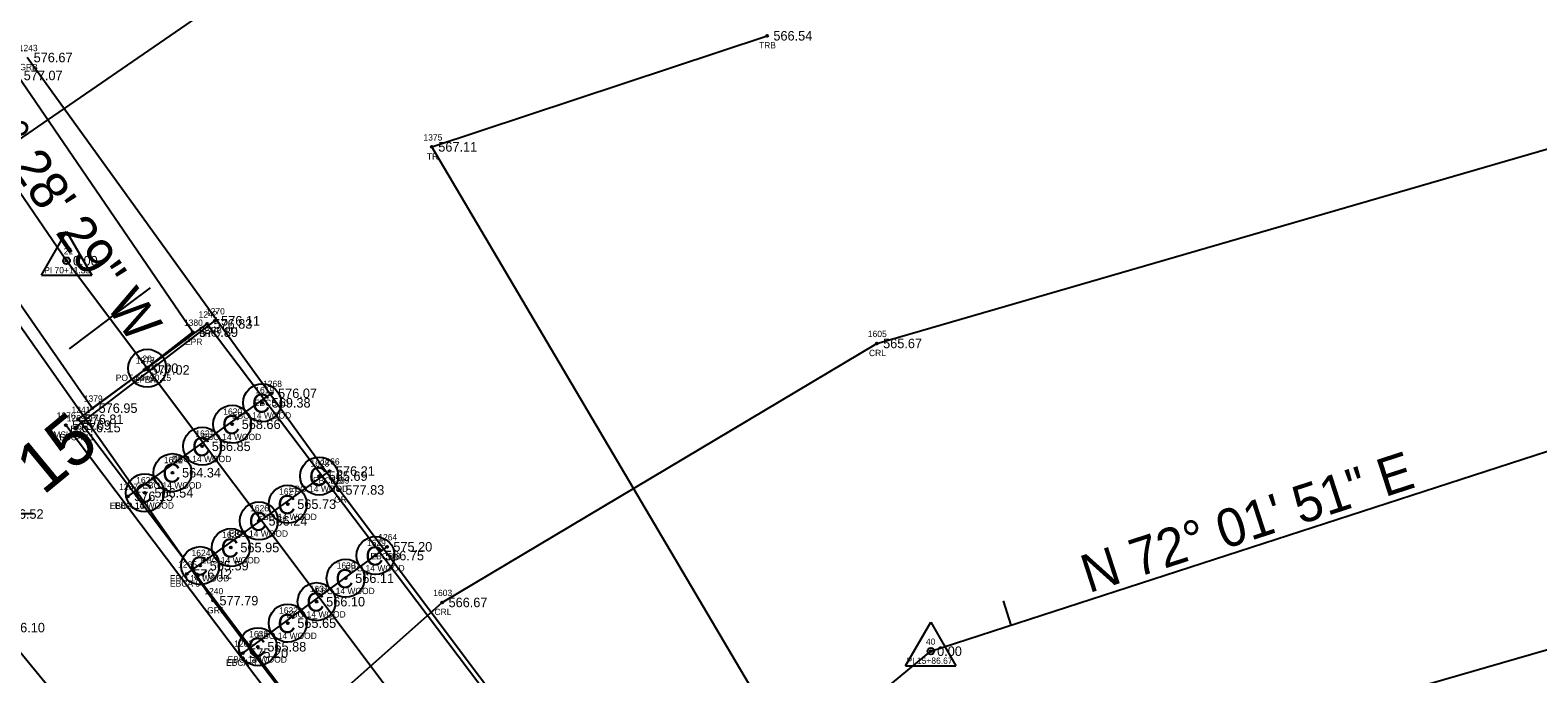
# Model space of a CAD drawing. Extents: x 1694813 to 1696862, y 1086485 to 1091027.
# Drawn here: x 1695795.8 to 1696033.6, y 1089100.2 to 1089201.7 of the extents above; entities that cross this region are included whole.
import ezdxf

# ---------------------------------------------------------------- set-up
doc = ezdxf.new("R2010")
doc.units = 0
for name, color, linetype in [('RD_EX_Bridge', 7, 'Continuous'), ('RD_EX_Bridge_txCode', 7, 'Continuous'), ('RD_EX_GuardRail', 7, 'Continuous'), ('RD_EX_GuardRail_txCode', 7, 'Continuous'), ('RD_EX_H2O', 7, 'Continuous'), ('RD_EX_H2O_txCode', 7, 'Continuous'), ('RD_EX_Misc', 7, 'Continuous'), ('RD_EX_Misc_txCode', 7, 'Continuous'), ('RD_EX_Road', 7, 'Continuous'), ('RD_EX_Road_txCode', 7, 'Continuous'), ('RD_EX_TX_Bridge_ELEV', 7, 'Continuous'), ('RD_EX_TX_GuardRail_ELEV', 7, 'Continuous'), ('RD_EX_TX_H2O_ELEV', 7, 'Continuous'), ('RD_EX_TX_Misc_ELEV', 7, 'Continuous'), ('RD_EX_TX_Road_ELEV', 7, 'Continuous'), ('RD_EX_TX_UT_ELEV', 7, 'Continuous'), ('RD_EX_TX_VEG_ELEV', 7, 'Continuous'), ('RD_EX_UT', 7, 'Continuous'), ('RD_EX_VEG', 7, 'Continuous'), ('RD_EX_VEG_txCode', 7, 'Continuous'), ('RD_HC_Cl', 7, 'Continuous'), ('RD_HC_Data', 7, 'Continuous'), ('RD_HC_Data_Tic', 7, 'Continuous'), ('RD_HC_Survey_ELEV', 7, 'Continuous'), ('RD_HC_TX_Sta50', 7, 'Continuous'), ('RD_HC_txCode', 7, 'Continuous'), ('RD_SMD_Locator', 7, 'Continuous')]:
    doc.layers.add(name, color=color, linetype=linetype)

msp = doc.modelspace()

# ---------------------------------------------------------------- linework, layer by layer
at = {"layer": 'RD_EX_Bridge'}
for p, q in [((1695802.9, 1089139.01), (1695824.88, 1089155.85)), ((1695811.17, 1089128.17), (1695833.87, 1089144.42)), ((1695820.47, 1089115.93), (1695842.99, 1089132.16)), ((1695829.32, 1089103.44), (1695852.05, 1089120.22))]:
    msp.add_line(p, q, dxfattribs=at)
msp.add_lwpolyline([(1695941.01, 1089000.23), (1695920.78, 1088984.87), (1695803.35, 1089140.32), (1695823.67, 1089155.36), (1695941.01, 1089000.23)], dxfattribs=at)
for centre in [(1695832.36, 1089142.92), (1695827.63, 1089139.53), (1695822.91, 1089136.06), (1695818.22, 1089131.9), (1695841.35, 1089131.36), (1695813.86, 1089128.72), (1695836.39, 1089126.93), (1695831.85, 1089124.29), (1695827.42, 1089120.09), (1695850.25, 1089118.83), (1695822.59, 1089117.24), (1695845.53, 1089115.25), (1695840.95, 1089111.56), (1695836.4, 1089108.18), (1695831.68, 1089104.45)]:
    msp.add_circle(centre, 3, dxfattribs=at)
at = {"layer": 'RD_EX_GuardRail'}
for points in [[(1695954.25, 1088939.4), (1695922.07, 1088982.8), (1695888.95, 1089026.55), (1695824.62, 1089111.72), (1695774.33, 1089183.16), (1695747.02, 1089230.32), (1695728.79, 1089274.77), (1695712.04, 1089332.59)], [(1695975.12, 1088955.36), (1695942.2, 1088999.47), (1695910.75, 1089040.94), (1695844.49, 1089129.18), (1695795.31, 1089197.37)]]:
    msp.add_lwpolyline(points, dxfattribs=at)
at = {"layer": 'RD_EX_H2O'}
for points in [[(1695741.44, 1088979.77), (1695766.31, 1089008.66), (1695772.21, 1089014.13), (1695837.09, 1089090.39), (1695860.76, 1089111.44), (1695929.31, 1089152.28), (1696035.3, 1089183.03), (1696164.17, 1089149.21), (1696221.7, 1089111.38), (1696248.95, 1089080.06), (1696273.19, 1089047.83), (1696283.59, 1089011.28), (1696295.68, 1088944.39)], [(1695520.92, 1088704.05), (1695627.53, 1088770.84), (1695697.51, 1088817.15), (1695757.08, 1088884.85), (1695828.4, 1088961.5), (1695887.69, 1089025.09), (1695910.13, 1089043.49), (1695963.83, 1089083.42), (1696041.69, 1089105.91), (1696137.07, 1089082.48), (1696174.24, 1089034.61), (1696185.76, 1089011.54), (1696200.45, 1088973.14), (1696214.06, 1088899.28)]]:
    msp.add_lwpolyline(points, dxfattribs=at)
at = {"layer": 'RD_EX_Misc'}
msp.add_line((1695918.59, 1088984.27), (1695801.38, 1089139.4), dxfattribs=at)
at = {"layer": 'RD_EX_Road'}
for points in [[(1695813.78, 1089148.1), (1695805.56, 1089142.08), (1695776.44, 1089183.94), (1695749.27, 1089231.88), (1695730.49, 1089275.72), (1695714.87, 1089332.12), (1695707.87, 1089381.72), (1695706.58, 1089435.34), (1695711.58, 1089484.26), (1695722.15, 1089537.59), (1695749.04, 1089634.88), (1695776.11, 1089730.43), (1695788.13, 1089777.42), (1695798.89, 1089826.76), (1695807.1, 1089870.03), (1695814.71, 1089923.3), (1695820.51, 1089978.16), (1695824.04, 1090019.79), (1695832.76, 1090119.06), (1695841.25, 1090216.76), (1695850.36, 1090314.41), (1695859.24, 1090411.82), (1695868.09, 1090511.63), (1695876.75, 1090608.38)], [(1695813.78, 1089148.1), (1695821.41, 1089154.05), (1695793.74, 1089194.54), (1695767.99, 1089240.85), (1695750.16, 1089282.55), (1695735.35, 1089335.84), (1695728.69, 1089383.6)]]:
    msp.add_lwpolyline(points, dxfattribs=at)
at = {"layer": 'RD_EX_UT'}
msp.add_line((1695792.25, 1089125.44), (1695796.27, 1089125.44), dxfattribs=at)
at = {"layer": 'RD_EX_VEG'}
for points in [[(1695767.04, 1087738.17), (1695850.84, 1087719.29), (1695876.92, 1087874.52), (1695886.77, 1087978.73), (1695882.04, 1088123.19), (1695966.35, 1088397.22), (1695987.61, 1088500.99), (1696016.82, 1088604.01), (1696023.94, 1088658.84), (1696026.75, 1088706.17), (1696020.44, 1088756.26), (1696012.04, 1088803.02), (1695995.69, 1088847.32), (1695967.16, 1088892.48), (1695790.95, 1089107.47), (1695767.01, 1089177.35), (1695741.24, 1089223.37), (1695720.39, 1089271.33), (1695703.52, 1089329.03), (1695695, 1089381.13)], [(1695933.86, 1087837.25), (1695947.67, 1087971.41), (1695951.18, 1088015.29), (1695955.07, 1088071.66), (1695974.95, 1088229.99), (1695984.06, 1088281.51), (1695991.57, 1088334), (1696002.15, 1088386.49), (1696032.05, 1088491.59), (1696059.12, 1088595.39), (1696074.06, 1088653.09), (1696077.62, 1088703.57), (1696070.4, 1088760.42), (1696059.88, 1088817.29), (1696044.37, 1088867.3), (1696013.5, 1088916.36), (1695990.24, 1088961.27), (1695859.14, 1089183.28), (1695912, 1089200.8)]]:
    msp.add_lwpolyline(points, dxfattribs=at)
at = {"layer": 'RD_HC_Cl'}
for p, q in [((1695801.51, 1089165.33), (1695790.19, 1089181.82)), ((1695971.3, 1088939.1), (1695801.51, 1089165.33)), ((1695937.83, 1089103.75), (1696039.29, 1089136.66)), ((1695799.79, 1088989.83), (1695937.83, 1089103.75))]:
    msp.add_line(p, q, dxfattribs=at)
at = {"layer": 'RD_HC_Data'}
for p, q in [((1695790.19, 1089181.82), (1695886.34, 1089247.84)), ((1695797.54, 1089163.04), (1695801.51, 1089169.92)), ((1695801.51, 1089169.92), (1695805.48, 1089163.04)), ((1695797.54, 1089163.04), (1695805.48, 1089163.04)), ((1695933.86, 1089101.46), (1695937.83, 1089108.34)), ((1695937.83, 1089108.34), (1695941.8, 1089101.46)), ((1695933.86, 1089101.46), (1695941.8, 1089101.46))]:
    msp.add_line(p, q, dxfattribs=at)
for centre, radius in [((1695801.51, 1089165.33), 0.529), ((1695814.23, 1089148.37), 3), ((1695814.23, 1089148.37), 0.282), ((1695937.83, 1089103.75), 0.529)]:
    msp.add_circle(centre, radius, dxfattribs=at)
at = {"layer": 'RD_HC_Data_Tic'}
for p, q in [((1695808.32, 1089156.25), (1695814.72, 1089161.05)), ((1695808.32, 1089156.25), (1695801.92, 1089151.45)), ((1695950.51, 1089107.86), (1695949.28, 1089111.67))]:
    msp.add_line(p, q, dxfattribs=at)
at = {"layer": 'RD_SMD_Locator'}
for centre in [(1695912, 1089200.8), (1695859.14, 1089183.28), (1695801.51, 1089165.33), (1695821.41, 1089154.05), (1695823.67, 1089155.36), (1695824.88, 1089155.85), (1695929.31, 1089152.28), (1695813.78, 1089148.1), (1695813.78, 1089148.1), (1695814.23, 1089148.37), (1695833.87, 1089144.42), (1695805.56, 1089142.08), (1695832.36, 1089142.92), (1695801.38, 1089139.4), (1695803.35, 1089140.32), (1695827.63, 1089139.53), (1695802.9, 1089139.01), (1695822.91, 1089136.06), (1695818.22, 1089131.9), (1695841.35, 1089131.36), (1695842.99, 1089132.16), (1695811.17, 1089128.17), (1695813.86, 1089128.72), (1695844.49, 1089129.18), (1695836.39, 1089126.93), (1695831.85, 1089124.29), (1695827.42, 1089120.09), (1695850.25, 1089118.83), (1695852.05, 1089120.22), (1695820.47, 1089115.93), (1695822.59, 1089117.24), (1695845.53, 1089115.25), (1695824.62, 1089111.72), (1695840.95, 1089111.56), (1695860.76, 1089111.44), (1695836.4, 1089108.18), (1695831.68, 1089104.45), (1695937.83, 1089103.75), (1695829.32, 1089103.44)]:
    msp.add_circle(centre, 0.15, dxfattribs=at)

# ---------------------------------------------------------------- texts
at = {"layer": 'RD_EX_Bridge'}
for p in [(1695830.73, 1089141.36), (1695826, 1089137.97), (1695821.28, 1089134.5), (1695816.59, 1089130.34), (1695839.72, 1089129.8), (1695812.22, 1089127.16), (1695834.76, 1089125.37), (1695830.22, 1089122.73), (1695825.79, 1089118.53), (1695820.96, 1089115.68), (1695848.62, 1089117.27), (1695843.89, 1089113.69), (1695839.31, 1089110), (1695834.77, 1089106.62), (1695830.05, 1089102.89)]:
    msp.add_text('C', height=3, dxfattribs=at).set_placement(p)
at = {"layer": 'RD_EX_Bridge_txCode'}
for s, p in [('1242', (1695822.33, 1089156.36)), ('1270', (1695823.49, 1089156.85)), ('EBCB 11', (1695822.37, 1089153.85)), ('BRC', (1695822.42, 1089153.36)), ('1619', (1695831.27, 1089144.42)), ('1268', (1695832.5, 1089145.42)), ('1241', (1695802.29, 1089141.32)), ('1620', (1695826.22, 1089141.03)), ('EBCB 10', (1695831.04, 1089142.42)), ('1269', (1695801.53, 1089140.01)), ('EBO 14 WOOD', (1695827.58, 1089140.42)), ('EBCA 11', (1695800.37, 1089137.01)), ('BRC', (1695802.1, 1089138.32)), ('1621', (1695821.82, 1089137.56)), ('EBO 14 WOOD', (1695822.85, 1089137.03)), ('1622', (1695816.85, 1089133.4)), ('EBO 14 WOOD', (1695818.13, 1089133.56)), ('1628', (1695839.98, 1089132.86)), ('1266', (1695841.6, 1089133.16)), ('1267', (1695809.8, 1089129.17)), ('1623', (1695812.49, 1089130.22)), ('EBO 14 WOOD', (1695813.44, 1089129.4)), ('EBCB 9', (1695840.37, 1089130.16)), ('1627', (1695835.02, 1089128.43)), ('EBO 14 WOOD', (1695836.57, 1089128.86)), ('EBCA 10', (1695808.31, 1089126.17)), ('EBO 14 WOOD', (1695809.08, 1089126.22)), ('1626', (1695830.46, 1089125.79)), ('EBO 14 WOOD', (1695831.61, 1089124.43)), ('EBO 14 WOOD', (1695827.08, 1089121.79)), ('1625', (1695826.05, 1089121.59)), ('1629', (1695848.88, 1089120.33)), ('1264', (1695850.68, 1089121.22)), ('1624', (1695821.22, 1089118.74)), ('EBO 14 WOOD', (1695822.64, 1089117.59)), ('EBCB 8', (1695849.43, 1089118.22)), ('EBO 14 WOOD', (1695817.81, 1089114.74)), ('1265', (1695819.1, 1089116.93)), ('1630', (1695844.12, 1089116.75)), ('EBO 14 WOOD', (1695845.47, 1089116.33)), ('EBCA 9', (1695817.82, 1089113.93)), ('1631', (1695839.86, 1089113.06)), ('EBO 14 WOOD', (1695840.75, 1089112.75)), ('1632', (1695835.03, 1089109.68)), ('EBO 14 WOOD', (1695836.17, 1089109.06)), ('1633', (1695830.31, 1089105.95)), ('EBO 14 WOOD', (1695831.62, 1089105.68)), ('1263', (1695827.95, 1089104.44)), ('EBCA 8', (1695826.66, 1089101.44)), ('EBO 14 WOOD', (1695826.9, 1089101.95))]:
    msp.add_text(s, height=1, dxfattribs=at).set_placement(p)
at = {"layer": 'RD_EX_GuardRail_txCode'}
for s, p in [('1243', (1695793.96, 1089198.37)), ('GRB', (1695794.06, 1089195.37)), ('1239', (1695843.15, 1089130.18)), ('GR', (1695843.71, 1089127.18)), ('1240', (1695823.24, 1089112.72)), ('GR1', (1695823.68, 1089109.72))]:
    msp.add_text(s, height=1, dxfattribs=at).set_placement(p)
at = {"layer": 'RD_EX_H2O_txCode'}
for s, p in [('1605', (1695927.9, 1089153.28)), ('CRL', (1695928.08, 1089150.28)), ('1603', (1695859.35, 1089112.44)), ('CRL', (1695859.54, 1089109.44))]:
    msp.add_text(s, height=1, dxfattribs=at).set_placement(p)
at = {"layer": 'RD_EX_Misc_txCode'}
for s, p in [('1276', (1695799.94, 1089140.4)), ('MSLB', (1695799.41, 1089137.4))]:
    msp.add_text(s, height=1, dxfattribs=at).set_placement(p)
at = {"layer": 'RD_EX_Road_txCode'}
for s, p in [('1380', (1695820.02, 1089155.05)), ('EPR', (1695820.18, 1089152.05)), ('1377', (1695812.43, 1089149.1)), ('1378', (1695812.43, 1089149.1)), ('EPRA', (1695812.06, 1089146.1)), ('EPLA', (1695812.08, 1089146.1)), ('1379', (1695804.22, 1089143.08)), ('EPL', (1695804.36, 1089140.08))]:
    msp.add_text(s, height=1, dxfattribs=at).set_placement(p)
at = {"layer": 'RD_EX_TX_Bridge_ELEV'}
for s, p in [('576.83', (1695824.67, 1089154.61)), ('576.11', (1695825.88, 1089155.1)), ('576.07', (1695834.87, 1089143.67)), ('569.38', (1695833.86, 1089142.17)), ('576.15', (1695803.9, 1089138.26)), ('576.81', (1695804.35, 1089139.57)), ('568.66', (1695829.13, 1089138.78)), ('566.85', (1695824.41, 1089135.31)), ('564.34', (1695819.72, 1089131.15)), ('576.21', (1695843.99, 1089131.41)), ('565.69', (1695842.85, 1089130.61)), ('576.15', (1695812.17, 1089127.42)), ('566.54', (1695815.36, 1089127.97)), ('565.73', (1695837.89, 1089126.18)), ('566.24', (1695833.35, 1089123.54)), ('565.95', (1695828.92, 1089119.34)), ('575.20', (1695853.05, 1089119.47)), ('566.75', (1695851.75, 1089118.08)), ('576.12', (1695821.47, 1089115.18)), ('565.59', (1695824.09, 1089116.49)), ('566.11', (1695847.03, 1089114.5)), ('566.10', (1695842.45, 1089110.81)), ('565.65', (1695837.9, 1089107.43)), ('575.20', (1695830.32, 1089102.69)), ('565.88', (1695833.18, 1089103.7))]:
    msp.add_text(s, height=1.5, dxfattribs=at).set_placement(p)
at = {"layer": 'RD_EX_TX_GuardRail_ELEV'}
for s, p in [('576.67', (1695796.31, 1089196.62)), ('577.83', (1695845.49, 1089128.43)), ('577.79', (1695825.62, 1089110.97))]:
    msp.add_text(s, height=1.5, dxfattribs=at).set_placement(p)
at = {"layer": 'RD_EX_TX_H2O_ELEV'}
for s, p in [('565.67', (1695930.31, 1089151.53)), ('566.67', (1695861.76, 1089110.69))]:
    msp.add_text(s, height=1.5, dxfattribs=at).set_placement(p)
at = {"layer": 'RD_EX_TX_Misc_ELEV'}
msp.add_text('575.69', height=1.5, dxfattribs=at).set_placement((1695802.38, 1089138.65))
at = {"layer": 'RD_EX_TX_Road_ELEV'}
for s, p in [('577.07', (1695794.74, 1089193.79)), ('576.89', (1695822.41, 1089153.3)), ('577.02', (1695814.78, 1089147.35)), ('577.02', (1695814.78, 1089147.35)), ('576.95', (1695806.56, 1089141.33))]:
    msp.add_text(s, height=1.5, dxfattribs=at).set_placement(p)
at = {"layer": 'RD_EX_TX_UT_ELEV'}
msp.add_text('566.52', height=1.5, dxfattribs=at).set_placement((1695791.74, 1089124.63))
at = {"layer": 'RD_EX_TX_VEG_ELEV'}
for s, p in [('566.54', (1695913, 1089200.05)), ('567.11', (1695860.14, 1089182.53)), ('566.10', (1695791.95, 1089106.72))]:
    msp.add_text(s, height=1.5, dxfattribs=at).set_placement(p)
at = {"layer": 'RD_EX_VEG_txCode'}
for s, p in [('TRB', (1695910.73, 1089198.8)), ('1375', (1695857.8, 1089184.28)), ('TR', (1695858.35, 1089181.28))]:
    msp.add_text(s, height=1, dxfattribs=at).set_placement(p)
at = {"layer": 'RD_HC_Data'}
for s, rotation, p in [('N 34%%d 28\' 29" W', 304.4747, (1695779.78, 1089198.73)), ('N 72%%d 01\' 51" E', 17.9692, (1695962.75, 1089112.88))]:
    msp.add_text(s, height=6, rotation=rotation, dxfattribs=at).set_placement(p)
at = {"layer": 'RD_HC_Survey_ELEV'}
for p in [(1695802.51, 1089164.58), (1695815.23, 1089147.62), (1695938.83, 1089103)]:
    msp.add_text('0.00', height=1.5, dxfattribs=at).set_placement(p)
at = {"layer": 'RD_HC_TX_Sta50'}
msp.add_text('15', height=8, rotation=39.5316, dxfattribs=at).set_placement((1695797.8, 1089128.22))
at = {"layer": 'RD_HC_txCode'}
for s, p in [('21', (1695801.06, 1089166.33)), ('PI 70+11.35', (1695797.97, 1089163.33)), ('20', (1695813.46, 1089149.37)), ('POT 69+90.15', (1695809.26, 1089146.37)), ('40', (1695937.06, 1089104.75)), ('PI 15+86.67', (1695934.01, 1089101.75))]:
    msp.add_text(s, height=1, dxfattribs=at).set_placement(p)

doc.saveas('drawing.dxf')
